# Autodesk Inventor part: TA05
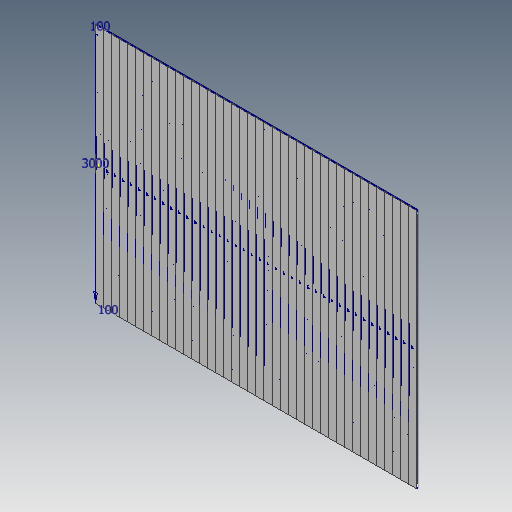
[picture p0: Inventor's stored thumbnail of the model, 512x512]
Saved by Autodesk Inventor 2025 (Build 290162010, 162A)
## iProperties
Created: 2024-10
Part Number: TA05
Material: Generico
Document SubType Name: Modeling
Designer: Michela.Gerbotto
Density: 1 g/cm^3
Appearance: Default
Author: Michela.Gerbotto
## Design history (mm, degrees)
sketch "Schizzo1"
  geometry: L1 (50, -1500)-(-50, -1500); L2 (-50, -1500)-(-50, 1500); L3 (-50, 1500)-(50, 1500); L4 (50, 1500)-(50, -1500); L5 (50, -1500)-(-50, 1500); L6 (-50, -1500)-(50, 1500); L7 (150, -1500)-(50, -1500); L8 (50, -1500)-(50, 1500); L9 (50, 1500)-(150, 1500); L10 (150, 1500)-(150, -1500); L11 (150, -1500)-(50, 1500); L12 (50, -1500)-(150, 1500); L13 (250, -1500)-(150, -1500); L14 (150, -1500)-(150, 1500); L15 (150, 1500)-(250, 1500); L16 (250, 1500)-(250, -1500); L17 (250, -1500)-(150, 1500); L18 (150, -1500)-(250, 1500); L19 (350, -1500)-(250, -1500); L20 (250, -1500)-(250, 1500); L21 (250, 1500)-(350, 1500); L22 (350, 1500)-(350, -1500); L23 (350, -1500)-(250, 1500); L24 (250, -1500)-(350, 1500); L25 (450, -1500)-(350, -1500); L26 (350, -1500)-(350, 1500); L27 (350, 1500)-(450, 1500); L28 (450, 1500)-(450, -1500); L29 (450, -1500)-(350, 1500); L30 (350, -1500)-(450, 1500); L31 (550, -1500)-(450, -1500); L32 (450, -1500)-(450, 1500); L33 (450, 1500)-(550, 1500); L34 (550, 1500)-(550, -1500); L35 (550, -1500)-(450, 1500); L36 (450, -1500)-(550, 1500); L37 (650, -1500)-(550, -1500); L38 (550, -1500)-(550, 1500); L39 (550, 1500)-(650, 1500); L40 (650, 1500)-(650, -1500); L41 (650, -1500)-(550, 1500); L42 (550, -1500)-(650, 1500); L43 (750, -1500)-(650, -1500); L44 (650, -1500)-(650, 1500); L45 (650, 1500)-(750, 1500); L46 (750, 1500)-(750, -1500); L47 (750, -1500)-(650, 1500); L48 (650, -1500)-(750, 1500); L49 (850, -1500)-(750, -1500); L50 (750, -1500)-(750, 1500); L51 (750, 1500)-(850, 1500); L52 (850, 1500)-(850, -1500); L53 (850, -1500)-(750, 1500); L54 (750, -1500)-(850, 1500); L55 (950, -1500)-(850, -1500); L56 (850, -1500)-(850, 1500); L57 (850, 1500)-(950, 1500); L58 (950, 1500)-(950, -1500); L59 (950, -1500)-(850, 1500); L60 (850, -1500)-(950, 1500); L61 (1050, -1500)-(950, -1500); L62 (950, -1500)-(950, 1500); L63 (950, 1500)-(1050, 1500); L64 (1050, 1500)-(1050, -1500)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; 118 further points
  constraints: 480 end point, 2 horizontal, 2 midpoint, 2 parallel, 1 collinear, 1 perpendicular, 428 other
  dimensions: "d0" = 100 distance of L2.end L3.end; "d1" = 3000 distance of L1.end L2.end; "d4" = 100 distance of L1.start L7.start
  node "Schizzo - Serie rettangolare1" dims "d4" = 100, "d7" = 10
extrude "Estrusione1" new body sketch "Schizzo1" distance "d9" = 10; taper "d10" = 0 deg
extrude "Estrusione2" new body sketch "Schizzo1" distance "d11" = 10; taper "d12" = 0 deg
extrude "Estrusione3" new body sketch "Schizzo1" distance "d13" = 10; taper "d14" = 0 deg
extrude "Estrusione4" new body sketch "Schizzo1" distance "d15" = 10; taper "d16" = 0 deg
extrude "Estrusione5" new body sketch "Schizzo1" distance "d17" = 10; taper "d18" = 0 deg
extrude "Estrusione6" new body sketch "Schizzo1" distance "d19" = 10; taper "d20" = 0 deg
node "Solido1"
node "Solido2"
node "Solido3"
node "Solido4"
node "Solido5"
node "Solido6"
